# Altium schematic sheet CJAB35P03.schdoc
size 127 x 101 mm
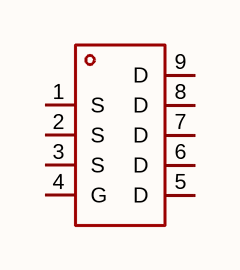
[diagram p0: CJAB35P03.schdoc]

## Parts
Q?  cjab35p03  [POWERPAK-1212-8_L3.0-W3.0-P0.65-LS3.3-BL]  (value not drawn)

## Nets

Not connected (* = marked no-connect by the designer): Q? 1(S) 2(S) 3(S) 4(G) 5(D) 6(D) 7(D) 8(D) 9(D)

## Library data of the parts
Q? = cjab35p03: 数量:1个P沟道;漏源电压(Vdss):30V;连续漏极电流(Id):35A;导通电阻(RDS(on)):9mΩ@10V;耗散功率(Pd):3W;阈值电压(Vgs(th)):2.5V;; Manufacturer: CJ(江苏长电/长晶); AddInBom: yes; ModelId: 74fc8db97a8d4d328d7f3b4acba39a5e; ModelTransform: 129.921,129.921,0,0,0,0,0,0,0; Number: 1个P沟道; Drain to Source Voltage: 30V; Current - Continuous Drain(Id): 35A; Pd - Power Dissipation: 3W; Gate Threshold Voltage (Vgs(th)): 2.5V; Gate Charge(Qg): 38nC; Input Capacitance(Ciss): 2.28nF; Reverse Transfer Capacitance (Crss@Vds): 278pF; Type: P沟道; Output Capacitance(Coss): 385pF; Vgs: ±20V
